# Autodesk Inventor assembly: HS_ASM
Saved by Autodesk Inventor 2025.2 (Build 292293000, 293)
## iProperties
Created: 2025-04
Part Number: HS_ASM
Description: NOT SPECIFIED
Document SubType Name: Assembly
Designer: BennF
Author: BennF
Revision Number: 2LAST_VERSION
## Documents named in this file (3)
- C:\Users\BennF\Nextcloud\Benutzer\CNC JarBeRi\existing parts\Electronics\Powersupply LRS-150-24\LRS-150(230808)\LRS-150(230808)\HS_ASM.iam
- C:\Users\BennF\Nextcloud\Benutzer\CNC JarBeRi\existing parts\Electronics\Powersupply LRS-150-24\LRS-150(230808)\LRS-150(230808)\PIN_1_1.ipt
- C:\Users\BennF\Nextcloud\Benutzer\CNC JarBeRi\existing parts\Electronics\Powersupply LRS-150-24\LRS-150(230808)\LRS-150(230808)\P2.ipt
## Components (2 placed, 2 different names)
1. PIN_1_1_22
2. P2_23
